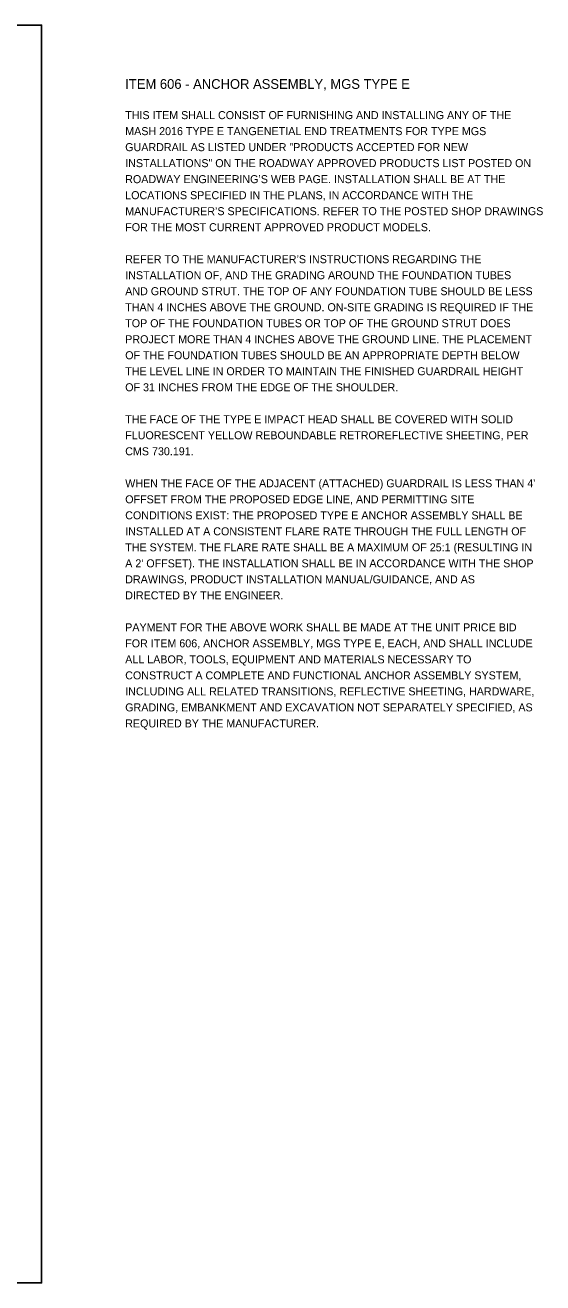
# Model space of a CAD drawing. Extents: x -6.7 to 44.8, y 0 to 42.6.
# Drawn here: x 33.71 to 42.77, y 0 to 22 of the extents above; entities that cross this region are included whole.
import ezdxf

# ---------------------------------------------------------------- set-up
doc = ezdxf.new("R2010")
doc.units = 0
for name, color, linetype in [('SH_Cut_Line', 7, 'Continuous'), ('SH_Text', 7, 'Continuous'), ('SV_X_Text', 7, 'Continuous')]:
    doc.layers.add(name, color=color, linetype=linetype)

msp = doc.modelspace()

# ---------------------------------------------------------------- linework, layer by layer
at = {"layer": 'SH_Cut_Line'}
msp.add_lwpolyline([(0, 0), (34, 0), (34, 22), (0, 22)], close=True, dxfattribs=at)

# ---------------------------------------------------------------- texts
at = {"layer": 'SH_Text'}
msp.add_text('ITEM 606 - ANCHOR ASSEMBLY, MGS TYPE E', height=0.17, dxfattribs=at).set_placement((35.462, 20.886))
at = {"layer": 'SV_X_Text'}
for s, p in [('THIS ITEM SHALL CONSIST OF FURNISHING AND INSTALLING ANY OF THE ', (35.462, 20.356)), ('MASH 2016 TYPE E TANGENETIAL END TREATMENTS FOR TYPE MGS ', (35.462, 20.076)), ('GUARDRAIL AS LISTED UNDER "PRODUCTS ACCEPTED FOR NEW ', (35.462, 19.796)), ('INSTALLATIONS" ON THE ROADWAY APPROVED PRODUCTS LIST POSTED ON ', (35.462, 19.516)), ('ROADWAY ENGINEERING’S WEB PAGE. INSTALLATION SHALL BE AT THE ', (35.462, 19.236)), ('LOCATIONS SPECIFIED IN THE PLANS, IN ACCORDANCE WITH THE ', (35.462, 18.956)), ('MANUFACTURER’S SPECIFICATIONS. REFER TO THE POSTED SHOP DRAWINGS ', (35.462, 18.676)), ('FOR THE MOST CURRENT APPROVED PRODUCT MODELS.', (35.462, 18.396)), ('REFER TO THE MANUFACTURER’S INSTRUCTIONS REGARDING THE ', (35.462, 17.836)), ('INSTALLATION OF, AND THE GRADING AROUND THE FOUNDATION TUBES ', (35.462, 17.556)), ('AND GROUND STRUT. THE TOP OF ANY FOUNDATION TUBE SHOULD BE LESS ', (35.462, 17.276)), ('THAN 4 INCHES ABOVE THE GROUND. ON-SITE GRADING IS REQUIRED IF THE ', (35.462, 16.996)), ('TOP OF THE FOUNDATION TUBES OR TOP OF THE GROUND STRUT DOES ', (35.462, 16.716)), ('PROJECT MORE THAN 4 INCHES ABOVE THE GROUND LINE. THE PLACEMENT ', (35.462, 16.436)), ('OF THE FOUNDATION TUBES SHOULD BE AN APPROPRIATE DEPTH BELOW ', (35.462, 16.156)), ('THE LEVEL LINE IN ORDER TO MAINTAIN THE FINISHED GUARDRAIL HEIGHT ', (35.462, 15.876)), ('OF 31 INCHES FROM THE EDGE OF THE SHOULDER.', (35.462, 15.596)), ('THE FACE OF THE TYPE E IMPACT HEAD SHALL BE COVERED WITH SOLID ', (35.462, 15.036)), ('FLUORESCENT YELLOW REBOUNDABLE RETROREFLECTIVE SHEETING, PER ', (35.462, 14.756)), ('CMS 730.191.', (35.462, 14.476)), ("WHEN THE FACE OF THE ADJACENT (ATTACHED) GUARDRAIL IS LESS THAN 4' ", (35.462, 13.916)), ('OFFSET FROM THE PROPOSED EDGE LINE, AND PERMITTING SITE ', (35.462, 13.636)), ('CONDITIONS EXIST: THE PROPOSED TYPE E ANCHOR ASSEMBLY SHALL BE ', (35.462, 13.356)), ('INSTALLED AT A CONSISTENT FLARE RATE THROUGH THE FULL LENGTH OF ', (35.462, 13.076)), ('THE SYSTEM. THE FLARE RATE SHALL BE A MAXIMUM OF 25:1 (RESULTING IN ', (35.462, 12.796)), ("A 2' OFFSET). THE INSTALLATION SHALL BE IN ACCORDANCE WITH THE SHOP ", (35.462, 12.516)), ('DRAWINGS, PRODUCT INSTALLATION MANUAL/GUIDANCE, AND AS ', (35.462, 12.236)), ('DIRECTED BY THE ENGINEER. ', (35.462, 11.956)), ('PAYMENT FOR THE ABOVE WORK SHALL BE MADE AT THE UNIT PRICE BID ', (35.462, 11.396)), ('FOR ITEM 606, ANCHOR ASSEMBLY, MGS TYPE E, EACH, AND SHALL INCLUDE ', (35.462, 11.116)), ('ALL LABOR, TOOLS, EQUIPMENT AND MATERIALS NECESSARY TO ', (35.462, 10.836)), ('CONSTRUCT A COMPLETE AND FUNCTIONAL ANCHOR ASSEMBLY SYSTEM, ', (35.462, 10.556)), ('INCLUDING ALL RELATED TRANSITIONS, REFLECTIVE SHEETING, HARDWARE, ', (35.462, 10.276)), ('GRADING, EMBANKMENT AND EXCAVATION NOT SEPARATELY SPECIFIED, AS ', (35.462, 9.996)), ('REQUIRED BY THE MANUFACTURER.', (35.462, 9.716))]:
    msp.add_text(s, height=0.14, dxfattribs=at).set_placement(p)

doc.saveas('drawing.dxf')
